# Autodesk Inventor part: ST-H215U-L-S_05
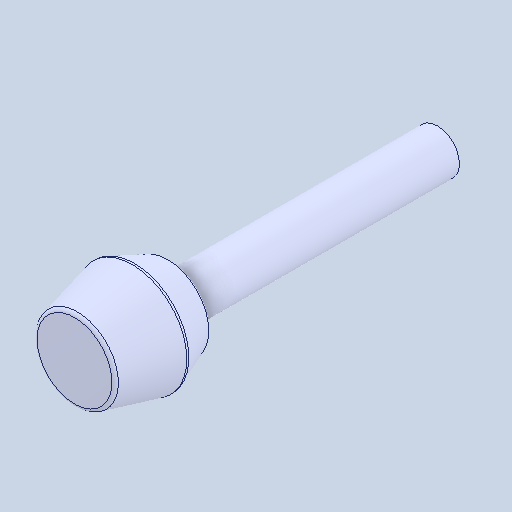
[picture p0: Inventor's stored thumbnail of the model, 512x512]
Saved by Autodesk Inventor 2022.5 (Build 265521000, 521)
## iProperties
Created: 2024-07
Part Number: ST-H215U-L-S_05
Material: 一般
Document SubType Name: Modeling
Designer: ImaoCorp
Density: 1 g/cm^3
Appearance: 既定
Author: ImaoCorp
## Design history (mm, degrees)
feature "ST-H215U-L-S_05"
node "ソリッド1"
